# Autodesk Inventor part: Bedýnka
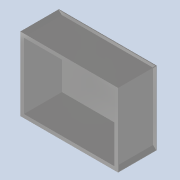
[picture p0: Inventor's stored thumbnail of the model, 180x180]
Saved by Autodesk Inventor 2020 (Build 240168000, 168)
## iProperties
Created: 2025-03
Part Number: Bedýnka
Material: Polypropylen
Document SubType Name: Modeling
Designer: doma
Density: 0.899 g/cm^3
Appearance: Hladká – středně šedá
Author: doma
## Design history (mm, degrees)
sketch "Náčrt1"
  geometry: L1 (-200, -150)-(200, -150); L2 (200, -150)-(200, 150); L3 (200, 150)-(-200, 150); L4 (-200, 150)-(-200, -150); L5 (-200, -150)-(200, 150); L6 (200, -150)-(-200, 150); 1 further point
  constraints: 12 end point, 2 midpoint, 2 parallel, 1 horizontal, 1 perpendicular
  dimensions: "d0" = 400 distance of L3.end L2.end; "d1" = 300 distance of L2.end L1.end
extrude "Vysunutí1" new body sketch "Náčrt1" distance "d2" = 170; taper "d3" = 0 deg
feature "Skořepina1" dims "d4" = 15
sketch "Náčrt2"
  geometry: L1 (-200, -150)-(-200, 150) reference; L2 (-200, 150)-(200, 150); L3 (200, 150)-(200, -150); L4 (200, -150)-(-200, -150); L5 (-200, -150)-(-200, 150); L6 (188, 138)-(-188, 138); L7 (-188, 138)-(-188, -138); L8 (-188, -138)-(188, -138); L9 (188, -138)-(188, 138); 2 further points
  constraints: 16 end point, 4 parallel, 2 perpendicular, 1 horizontal, 3 other
  dimensions: "d5" = 12 distance between parallel lines of L2 L6
extrude "Vysunutí2" cut sketch "Náčrt2" distance "d6" = 12; taper "d7" = 0 deg
feature "Skořepina2" dims "d8" = 3
sketch "Náčrt3"
  geometry: L1 (-185, -135)-(-200, -150); L2 (-200, 150)-(-200, -150) reference; L3 (-184.028, -131.906)-(-203.094, -150.972); L4 (-203.094, -150.972)-(-200.972, -153.094); L5 (-200.972, -153.094)-(-181.906, -134.028); L6 (-181.906, -134.028)-(-184.028, -131.906); L7 (-184.028, -131.906)-(-200.972, -153.094); L8 (-203.094, -150.972)-(-181.906, -134.028); L9 (-185, -135)-(-185, 135) reference; L10 (185, -135)-(-185, -135) reference; L11 (-200, -150)-(200, -150) reference; 6 further points
  constraints: 14 end point, 3 midpoint, 2 parallel, 1 perpendicular
  dimensions: "d10" = 3 distance of L4.end L3.end
extrude "Vysunutí3" join sketch "Náčrt3" stored distance "d11" = 12; taper "d12" = 0 deg
mirror "Zrcadlit1"
mirror "Zrcadlit2"
sketch "Náčrt4"
  geometry: C1 r 2.067 at (97.879, 6) reference; C2 r 2.067 at (297.879, 6) reference; C3 r 2.75 at (297.879, 6); C4 r 2.75 at (97.879, 6); 1 further point
  constraints: 2 centre point, 2 coincident
  dimensions: "d13" = 5.5 diameter of C3; "d14" = 5.5 diameter of C4
extrude "Vysunutí4" cut sketch "Náčrt4" distance "d15" = 10; taper "d16" = 0 deg
node "Těleso1"
node "Referenční1"
node "Referenční2"
